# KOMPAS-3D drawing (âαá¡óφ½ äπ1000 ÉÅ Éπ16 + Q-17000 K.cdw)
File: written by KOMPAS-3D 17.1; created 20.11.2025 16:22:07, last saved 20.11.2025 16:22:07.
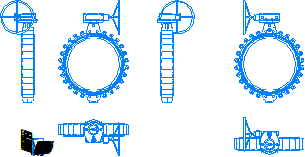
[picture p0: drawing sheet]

Sheet 1: A4, portrait

Title block, sheet 1: name: Гранвел Ду1000; material: Сталь 10  ГОСТ 1050-88; mass: 1192,85; sheets: 1; sheet format: A4

Views: Проекционный вид 3, Проекционный вид 4, Проекционный вид 6
Referenced files in \\adlc.lan\data\АДЛ_ПКД\3D-модели\ADL production\Дисковые поворотные затворы ГРАНВЭЛ\с резьбовыми проушинами с китайским редуктором Ру 16\KOMPAS 3D\: Гранвэл Ду1000 РП Ру16 + Q-17000 K.m3d
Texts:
  Andrey
  АДЛ
Dimensions and other numbers on the sheet: 1:1; 1; 1192,85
